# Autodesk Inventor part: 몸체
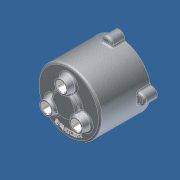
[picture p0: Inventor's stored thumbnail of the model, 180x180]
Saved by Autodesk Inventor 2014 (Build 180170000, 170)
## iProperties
Created: 2012-05
Part Number: 몸체
Document SubType Name: 모델링
Designer: SeoGD™
Material: 알루미늄 6061
Density: 2.71 g/cm^3
Appearance: 알루미늄 - 평지
Mass: 475.553 g
Surface Area: 687.661 cm^2
Volume: 175.481 cm^3
변환 표준: STEP AP214IS
파일 이름: C:\Users\SeoGD\Desktop\?쒗뿕\紐몄껜.stp
전처리기: Build: 253, Release: 2010 SP1 - Date: Wed 07/29/2009
전송 단위: 밀리미터
불확실성: 0.01
Author: SeoGD™
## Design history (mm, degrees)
sketch "스케치2"
  geometry: C1 r 50 at (0, 0); 1 further point
  constraints: 1 centre point, 1 coincident
  dimensions: "d9" = 100 diameter of C1
extrude "돌출2" new body sketch "스케치2" distance "d10" = 80; taper "d11" = 0 deg
feature "쉘1" dims "d12" = 5
sketch "스케치3" dims "d13" = 55
  geometry: C1 r 7.5 at (0, 27.5); C2 r 12.5 at (0, 27.5); 2 further points
  constraints: 2 centre point, 2 coincident, 2 vertical alignment, 2 other
  dimensions: "d14" = 15 diameter of C1; "d15" = 25 diameter of C2
extrude "돌출3" join sketch "스케치3" distance "d16" = 12; taper "d17" = -10 deg
hole "구멍2" diameter "d20" = 15; stored, may be unused: countersink angle "d24" = 90 deg, drill point angle "d26" = 118 deg; dims "d18" = 10, "d19" = 10, "d21" = 6, "d22" = 4, "d23" = 2, "d25" = 15
chamfer "모따기1" distance "d27" = 1; stored, may be unused: second distance "d28" = 2, angle "d29" = 45 deg
sketch "스케치4"
  geometry: L1 (0, 0)-(0, 88); L2 (0, 70)-(13.16, 70); L3 (-45, 75)-(45, 75) reference; L4 (-50, 80)-(50, 80) reference; L5 (13.16, 70)-(14.5, 75); L6 (20, 80)-(20, 88); L7 (20, 88)-(0, 88); L8 (20, 80)-(14.5, 75)
  constraints: 12 end point, 3 point on line, 2 perpendicular, 1 vertical
  dimensions: "d34" = 40 diameter of L6 L1; "d35" = 105 deg angle of L5 L3; "d36" = 5 distance between parallel lines of L2 L3; "d37" = 8 distance between parallel lines of L7 L4; "d51" = 29 diameter of L5.end L1
revolve "회전1" sketch "스케치4" stored, may be unused: angle "d38" = 90 deg
hole "구멍3" diameter "d41" = 15; stored, may be unused: countersink angle "d45" = 90 deg, drill point angle "d47" = 0 deg; dims "d39" = 10, "d40" = 10, "d42" = 6, "d43" = 22, "d44" = 13, "d46" = 15
chamfer "모따기2" distance "d48" = 1; stored, may be unused: second distance "d49" = 2, angle "d50" = 45 deg
fillet "모깎기1" dims "d52" = 3
fillet "모깎기2" dims "d53" = 3, "d72" = 0.2
sketch "스케치5"
  geometry: A1 r 50 centre (0, 0) between (50, 0) and (-8.074, 49.344) reference; A2 r 8.5 centre (0, 52) between (8.074, 49.344) and (-8.074, 49.344); 1 further point
  constraints: 5 point on circle, 1 centre point, 1 horizontal alignment
  dimensions: "d54" = 90 deg dimension on point (0, 0) A2.centre A1.start; "d55" = 52 distance of A2.centre point (0, 0); "d56" = 17 diameter of A2
extrude "돌출4" join sketch "스케치5" distance "d57" = 20; taper "d58" = 0 deg
fillet "모깎기3" dims "d59" = 3
hole "구멍4" diameter "d62" = 4.134; stored, may be unused: countersink angle "d66" = 90 deg, drill point angle "d68" = 118 deg; dims "d60" = 10, "d61" = 10, "d63" = 12, "d64" = 22, "d65" = 13, "d67" = 15
sketch "스케치6"
  geometry: C1 r 47 at (0, 0) reference; C2 r 42.5 at (0, 0); 1 further point
  constraints: 1 centre point, 1 coincident, 1 other
  dimensions: "d73" = 85 diameter of C2
feature "엠보싱1" sketch "스케치6" dims "d74" = 1, "d75" = 0
node "솔리드1"
node "솔리드 본체"
node "곡면 본체"
pattern_circular "원형 패턴1" dims "d31" = 360 deg
pattern_circular "원형 패턴2" dims "d70" = 360 deg
node "솔리드2"
